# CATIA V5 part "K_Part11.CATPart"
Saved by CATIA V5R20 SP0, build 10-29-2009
Part number: Logement_Verin
Bounding box of the stored display mesh (mm): x 4.5 to 14.5, y -7.423 to 120.203, z -7.423 to 14.472
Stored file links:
  G:\Khaled_CFAO_2011\SIL\SIL_GR1\mneves\Khaled\CAD_CATIA_Modifie\K_Part11.CATPart
  G:\Khaled_CFAO_2011\SIL\SIL_GR1\mneves\Khaled\CAD_CATIA_Modifie\K_AssPince_A_Bois.CATProduct
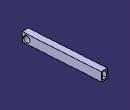
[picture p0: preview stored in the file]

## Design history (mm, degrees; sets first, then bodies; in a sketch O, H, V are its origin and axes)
External parameters (linked from other documents)
  External.Distance_Inter_Pivot = 200 mm
  `External.Epaisseur_LogementVérin` = 10 mm
  `External.Epaisseur_Vérin` = 6 mm
Set1
  Plane1: linked copy from another document
  Line1: linked copy from another document
  Point1: linked copy from another document
Body1 (main body)
  Sketch1 on Plane1, origin (9.5, 0, 0), H (0, 1, 0), V (0, 0, 1)
    line L1 (-7.423, 6.5497) -> (119.3297, 14.4718)
    line L2 (119.3297, 14.4718) -> (120.203, 0.499)
    line L3 (120.203, 0.499) -> (-6.5497, -7.423)
    line L4 (-6.5497, -7.423) -> (-7.423, 6.5497)
    circle A1 centre (0, 0) radius 5
    point P5 (0, 0)
    reference projected point E1 (0, 0) from Point1
    reference projected line E2 (0, 0) -> (119.7663, 7.4854) from Line1
    reference projected line E3 (0, 0) -> (119.7663, 7.4854) from Line1
    reference projected point E4 (0, 0) from Point1
    radius A1 = 5 {= External.Distance_Inter_Pivot /40}
    distance E2 L1 = 7 {= External.Distance_Inter_Pivot /40+External.Distance_Inter_Pivot /100}
    distance E3 L3 = 7 {= External.Distance_Inter_Pivot /40+External.Distance_Inter_Pivot /100}
    distance E4 L4 = 7 {= External.Distance_Inter_Pivot /40+External.Distance_Inter_Pivot /100}
    distance L4 L2 = 127 {= External.Distance_Inter_Pivot -External.Distance_Inter_Pivot /2.5+External.Distance_Inter_Pivot /40+External.Distance_Inter_Pivot /100}
    perpendicularity: L2 L1, L3 L4
    coincidence: E1 P5
  Pad1: profile Sketch1, direction (1, 0, 0), length 5 {= `External.Epaisseur_LogementVérin` /2}, mirrored extent
  Sketch2 on face of Pad1 from Sketch1.L2, origin (0, 119.7663, 7.4854), H (-1, 0, 0), V (0, -0.0624, 0.9981)
    line L1 (-12.5, 5) -> (-6.5, 5)
    line L2 (-6.5, 5) -> (-6.5, -5)
    line L3 (-6.5, -5) -> (-12.5, -5)
    line L4 (-12.5, -5) -> (-12.5, 5)
    reference projected line E1 (-4.5, -7) -> (-4.5, 7) from edge [start face of Pad1 | face of Pad1 from Sketch1.L2]
    reference projected line E2 (-4.5, -7) -> (-14.5, -7) from edge [face of Pad1 from Sketch1.L2 | face of Pad1 from Sketch1.L3]
    reference projected line E3 (-4.5, 7) -> (-14.5, 7) from edge [face of Pad1 from Sketch1.L1 | face of Pad1 from Sketch1.L2]
    distance L2 E1 = 2 {= `External.Epaisseur_LogementVérin` /2-`External.Epaisseur_Vérin` /2}
    distance L4 L2 = 6 {= `External.Epaisseur_Vérin`}
    distance L3 E2 = 2 {= External.Distance_Inter_Pivot /100}
    distance E3 L1 = 2 {= External.Distance_Inter_Pivot /100}
    horizontal: L1 H, L3 H
    vertical: L2 V, L4 V
  Pocket1: profile Sketch2, direction (0, -0.9981, -0.0624), length 113 {= External.Distance_Inter_Pivot -External.Distance_Inter_Pivot /2.5-External.Distance_Inter_Pivot /40-External.Distance_Inter_Pivot /100}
